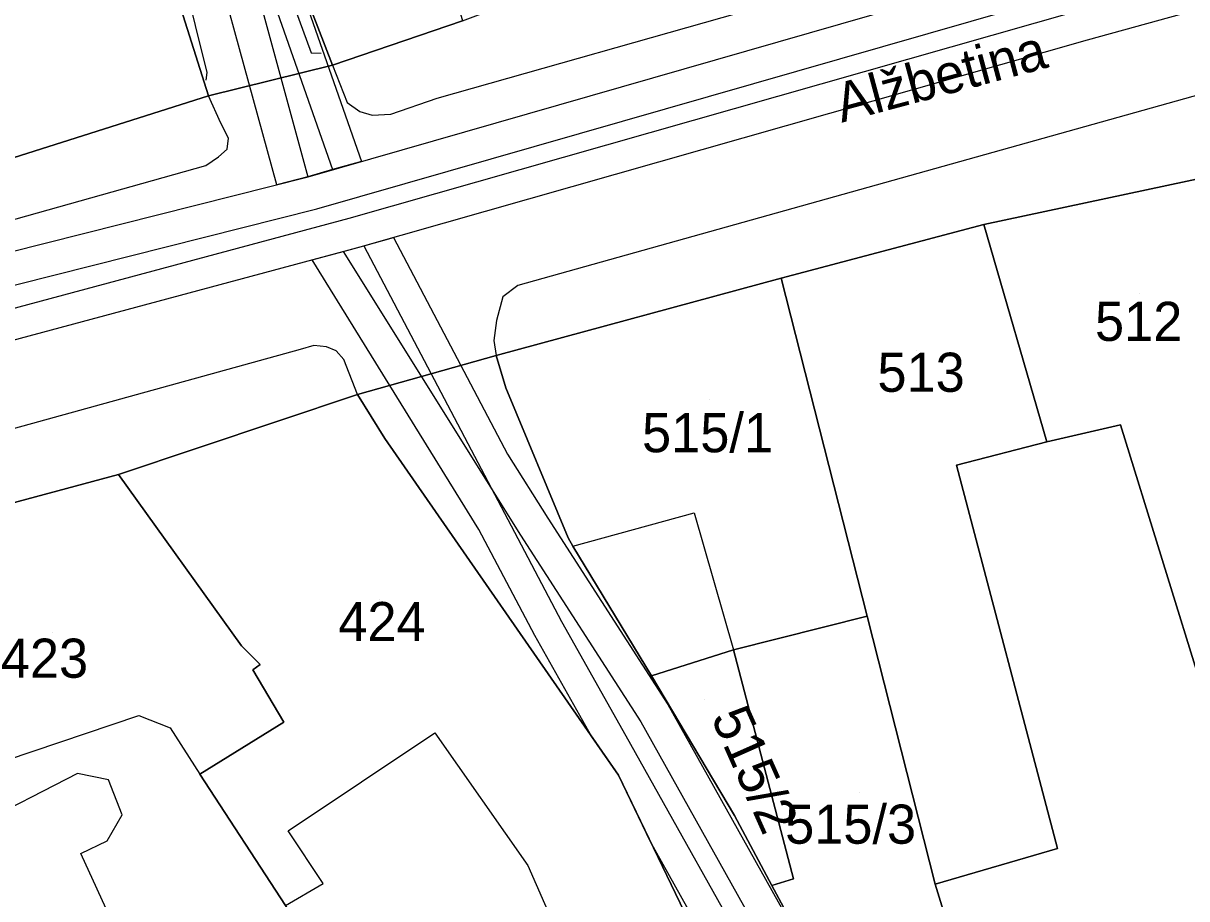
# Model space of a CAD drawing. Extents: x -263423 to -261326, y -1240067 to -1237864.
# Drawn here: x -263093.1 to -263033.7, y -1239708 to -1239663.3 of the extents above; entities that cross this region are included whole.
import ezdxf

# ---------------------------------------------------------------- set-up
doc = ezdxf.new("R2010")
doc.units = 0
for name, color, linetype in [('body_kn', 7, 'Continuous'), ('kladpar_druhypozemkov', 7, 'Continuous'), ('kladpar_hranice', 7, 'Continuous'), ('kladpar_parcelnecisla', 7, 'Continuous'), ('kladpar_plochy', 7, 'Continuous'), ('popisy', 7, 'Continuous'), ('tarchy_linie', 7, 'Continuous'), ('zappar_hrandruhpozemk', 7, 'Continuous')]:
    doc.layers.add(name, color=color, linetype=linetype)

msp = doc.modelspace()

# ---------------------------------------------------------------- linework, layer by layer
at = {"layer": 'body_kn'}
for p, q in [((-263038.78, -1239664.15), (-263038.78, -1239664.15)), ((-263078.42, -1239664.79), (-263078.42, -1239664.79)), ((-263077.91, -1239664.8), (-263077.91, -1239664.8)), ((-263077.34, -1239665.42), (-263077.34, -1239665.42)), ((-263077.34, -1239665.42), (-263077.34, -1239665.42)), ((-263083.76, -1239665.8), (-263083.76, -1239665.8)), ((-263083.8, -1239666.19), (-263083.8, -1239666.19)), ((-263083.66, -1239666.98), (-263083.66, -1239666.98)), ((-263071.98, -1239667.1), (-263071.98, -1239667.1)), ((-263076.58, -1239667.33), (-263076.58, -1239667.33)), ((-263075.94, -1239667.78), (-263075.94, -1239667.78)), ((-263083.03, -1239668.38), (-263083.03, -1239668.38)), ((-263075.3, -1239667.98), (-263075.3, -1239667.98)), ((-263074.35, -1239667.92), (-263074.35, -1239667.92)), ((-263082.65, -1239669.15), (-263082.65, -1239669.15)), ((-263083.16, -1239670.1), (-263083.16, -1239670.1)), ((-263082.71, -1239669.72), (-263082.71, -1239669.72)), ((-263083.8, -1239670.54), (-263083.8, -1239670.54)), ((-263077.34, -1239670.76), (-263077.34, -1239670.76)), ((-263075.85, -1239670.34), (-263075.85, -1239670.34)), ((-263078.59, -1239671.12), (-263078.59, -1239671.12)), ((-263078.58, -1239671.12), (-263078.58, -1239671.12)), ((-263080.18, -1239671.53), (-263080.18, -1239671.53)), ((-263078.14, -1239672.76), (-263078.14, -1239672.76)), ((-263076.48, -1239673.23), (-263076.48, -1239673.23)), ((-263044.06, -1239673.56), (-263044.06, -1239673.56)), ((-263044.06, -1239673.56), (-263044.06, -1239673.56)), ((-263074.22, -1239674.23), (-263074.22, -1239674.23)), ((-263074.22, -1239674.23), (-263074.22, -1239674.23)), ((-263076.78, -1239674.94), (-263076.78, -1239674.94)), ((-263076.78, -1239674.94), (-263076.78, -1239674.94)), ((-263076.06, -1239674.75), (-263076.06, -1239674.75)), ((-263075.73, -1239674.66), (-263075.73, -1239674.66)), ((-263075.73, -1239674.66), (-263075.73, -1239674.66)), ((-263078.38, -1239675.37), (-263078.38, -1239675.37)), ((-263067.87, -1239676.68), (-263067.87, -1239676.68)), ((-263054.41, -1239676.31), (-263054.41, -1239676.31)), ((-263054.41, -1239676.31), (-263054.41, -1239676.31)), ((-263068.64, -1239677.25), (-263068.64, -1239677.25)), ((-263068.96, -1239678.46), (-263068.96, -1239678.46)), ((-263078.28, -1239679.75), (-263078.28, -1239679.75)), ((-263069.09, -1239679.48), (-263069.09, -1239679.48)), ((-263078.99, -1239679.94), (-263078.99, -1239679.94)), ((-263077.64, -1239679.82), (-263077.64, -1239679.82)), ((-263077.14, -1239680.01), (-263077.14, -1239680.01)), ((-263068.97, -1239680.25), (-263068.97, -1239680.25)), ((-263076.75, -1239680.46), (-263076.75, -1239680.46)), ((-263068.47, -1239681.91), (-263068.47, -1239681.91)), ((-263076.06, -1239682.25), (-263076.06, -1239682.25)), ((-263076.06, -1239682.25), (-263076.06, -1239682.25)), ((-263037.08, -1239683.79), (-263037.08, -1239683.79)), ((-263074.66, -1239684.49), (-263074.66, -1239684.49)), ((-263040.85, -1239684.66), (-263040.85, -1239684.66)), ((-263068.39, -1239685.29), (-263068.39, -1239685.29)), ((-263045.45, -1239685.85), (-263045.45, -1239685.85)), ((-263088.26, -1239686.33), (-263088.26, -1239686.33)), ((-263088.26, -1239686.33), (-263088.26, -1239686.33)), ((-263066.33, -1239688.56), (-263066.33, -1239688.56)), ((-263058.85, -1239688.29), (-263058.85, -1239688.29)), ((-263069.85, -1239689.14), (-263069.85, -1239689.14)), ((-263067.73, -1239689.43), (-263067.73, -1239689.43)), ((-263065.3, -1239689.57), (-263065.3, -1239689.57)), ((-263065.05, -1239689.99), (-263065.05, -1239689.99)), ((-263065.05, -1239689.99), (-263065.05, -1239689.99)), ((-263065.63, -1239693.84), (-263065.63, -1239693.84)), ((-263050.02, -1239693.58), (-263050.02, -1239693.58)), ((-263067, -1239694.56), (-263067, -1239694.56)), ((-263081.98, -1239695.09), (-263081.98, -1239695.09)), ((-263056.85, -1239695.29), (-263056.85, -1239695.29)), ((-263056.85, -1239695.29), (-263056.85, -1239695.29)), ((-263081.41, -1239696.31), (-263081.41, -1239696.31)), ((-263081.02, -1239696.05), (-263081.02, -1239696.05)), ((-263061.03, -1239696.62), (-263061.03, -1239696.62)), ((-263061.03, -1239696.62), (-263061.03, -1239696.62)), ((-263060.2, -1239698.08), (-263060.2, -1239698.08)), ((-263087.22, -1239698.64), (-263087.22, -1239698.64)), ((-263085.63, -1239699.28), (-263085.63, -1239699.28)), ((-263079.82, -1239698.99), (-263079.82, -1239698.99)), ((-263061.59, -1239698.97), (-263061.59, -1239698.97)), ((-263072.11, -1239699.54), (-263072.11, -1239699.54)), ((-263064.09, -1239699.73), (-263064.09, -1239699.73)), ((-263062.34, -1239699.68), (-263062.34, -1239699.68)), ((-263090.36, -1239701.61), (-263090.36, -1239701.61)), ((-263084.11, -1239701.65), (-263084.11, -1239701.65)), ((-263062.73, -1239701.69), (-263062.73, -1239701.69)), ((-263088.77, -1239701.94), (-263088.77, -1239701.94)), ((-263088.07, -1239703.73), (-263088.07, -1239703.73)), ((-263056.8, -1239703.76), (-263056.8, -1239703.76)), ((-263079.59, -1239704.54), (-263079.59, -1239704.54)), ((-263088.84, -1239705.06), (-263088.84, -1239705.06)), ((-263061.08, -1239705.11), (-263061.08, -1239705.11)), ((-263090.19, -1239705.7), (-263090.19, -1239705.7)), ((-263040.29, -1239705.44), (-263040.29, -1239705.44)), ((-263040.29, -1239705.44), (-263040.29, -1239705.44)), ((-263067.35, -1239706.32), (-263067.35, -1239706.32)), ((-263053.79, -1239706.99), (-263053.79, -1239706.99)), ((-263077.81, -1239707.23), (-263077.81, -1239707.23)), ((-263054.89, -1239707.33), (-263054.89, -1239707.33)), ((-263046.55, -1239707.26), (-263046.55, -1239707.26))]:
    msp.add_line(p, q, dxfattribs=at)
at = {"layer": 'kladpar_druhypozemkov'}
for p, q in [((-263036.09, -1239677.08), (-263036.09, -1239677.08)), ((-263047.51, -1239680.02), (-263047.51, -1239680.02)), ((-263058.07, -1239682.49), (-263058.07, -1239682.49)), ((-263074.94, -1239692.7), (-263074.94, -1239692.7)), ((-263091.64, -1239694.43), (-263091.64, -1239694.43)), ((-263058.33, -1239697.85), (-263058.33, -1239697.85)), ((-263050.4, -1239702.57), (-263050.4, -1239702.57))]:
    msp.add_line(p, q, dxfattribs=at)
at = {"layer": 'kladpar_hranice'}
for points in [[(-263089.13, -1239646.3), (-263087.57, -1239654.65), (-263083.66, -1239666.98), (-263102.19, -1239672.87), (-263104.68, -1239658.71), (-263104.81, -1239658), (-263105.49, -1239653.48), (-263107, -1239647.48), (-263105.73, -1239647.36), (-263103.75, -1239647.24), (-263089.13, -1239646.3)], [(-263070.69, -1239663.16), (-263077.34, -1239665.42), (-263082.9, -1239650.98), (-263082.64, -1239650.86), (-263078.94, -1239649.73), (-263074.91, -1239648.54), (-263070.69, -1239663.16)], [(-263173.05, -1239691.46), (-263143.93, -1239683.63), (-263134.03, -1239681.02), (-263132.76, -1239680.64), (-263130.92, -1239680.26), (-263121.67, -1239678.18), (-263113.17, -1239675.87), (-263110.23, -1239675.06), (-263102.19, -1239672.87), (-263083.66, -1239666.98), (-263077.34, -1239665.42), (-263070.69, -1239663.16), (-263068.84, -1239662.46), (-263064.69, -1239661.08), (-263061.56, -1239660.4), (-263059.64, -1239659.9), (-263058.11, -1239659.46), (-263052.62, -1239657.71), (-263049.81, -1239656.96), (-263044.38, -1239655.39), (-263040.1, -1239654.14), (-263037.61, -1239653.45), (-263034.48, -1239652.64), (-263029.18, -1239651.14)], [(-263082.9, -1239650.98), (-263077.34, -1239665.42), (-263083.66, -1239666.98), (-263087.57, -1239654.65)], [(-263032.63, -1239671.13), (-263044.06, -1239673.56), (-263054.41, -1239676.31), (-263068.97, -1239680.25), (-263076.06, -1239682.25), (-263088.26, -1239686.33), (-263109.85, -1239692.14), (-263111.38, -1239692.39), (-263119.82, -1239694.51), (-263121.61, -1239695.01), (-263130.26, -1239696.9), (-263130.33, -1239696.59), (-263132.49, -1239697.1), (-263132.36, -1239697.54), (-263132.93, -1239697.67), (-263136.1, -1239698.43), (-263136.29, -1239698.5), (-263136.42, -1239698.18), (-263138.83, -1239698.75), (-263138.77, -1239699.07), (-263146.95, -1239701.04), (-263158.18, -1239703.72)], [(-263032.63, -1239671.13), (-263029.01, -1239691.42), (-263028.92, -1239700.15), (-263024.63, -1239712.22), (-263023.17, -1239716.24), (-263018.7, -1239730.16), (-263018.89, -1239730.86), (-263029.02, -1239727.36), (-263028.76, -1239726.41), (-263029.76, -1239720.92), (-263027.85, -1239720.48), (-263026.44, -1239718.2), (-263037.08, -1239683.79), (-263040.85, -1239684.66), (-263044.06, -1239673.56), (-263032.63, -1239671.13)], [(-263044.06, -1239673.56), (-263040.85, -1239684.66), (-263045.45, -1239685.85), (-263040.29, -1239705.44), (-263046.55, -1239707.26), (-263050.02, -1239693.58), (-263054.41, -1239676.31), (-263044.06, -1239673.56)], [(-263054.41, -1239676.31), (-263050.02, -1239693.58), (-263056.85, -1239695.29), (-263061.03, -1239696.62), (-263065.05, -1239689.99), (-263065.3, -1239689.57), (-263068.47, -1239681.91), (-263068.97, -1239680.25), (-263054.41, -1239676.31)], [(-263029.37, -1239734.56), (-263046.25, -1239727.85), (-263052.8, -1239721.7), (-263056.66, -1239714.28), (-263062.73, -1239701.69), (-263074.66, -1239684.49), (-263076.06, -1239682.25), (-263068.97, -1239680.25), (-263068.47, -1239681.91), (-263065.3, -1239689.57), (-263065.05, -1239689.99), (-263061.03, -1239696.62), (-263056.8, -1239703.76), (-263054.89, -1239707.33), (-263053.47, -1239709.96), (-263051.55, -1239713.54), (-263048.19, -1239718.6), (-263045.41, -1239721.07), (-263045.01, -1239721.42), (-263036.09, -1239724.78), (-263032.84, -1239725.88)], [(-263076.06, -1239682.25), (-263074.66, -1239684.49), (-263062.73, -1239701.69), (-263056.66, -1239714.28), (-263068.24, -1239723.85), (-263068.88, -1239724.42), (-263072.12, -1239720.58), (-263078.72, -1239710.03), (-263079.73, -1239708.36), (-263084.11, -1239701.65), (-263079.82, -1239698.99), (-263081.41, -1239696.31), (-263081.02, -1239696.05), (-263081.98, -1239695.09), (-263088.26, -1239686.33), (-263076.06, -1239682.25)], [(-263040.29, -1239705.44), (-263045.45, -1239685.85), (-263040.85, -1239684.66), (-263037.08, -1239683.79), (-263026.44, -1239718.2), (-263027.85, -1239720.48), (-263029.76, -1239720.92), (-263028.76, -1239726.41), (-263029.02, -1239727.36), (-263032.84, -1239725.88), (-263036.09, -1239724.78), (-263045.01, -1239721.42), (-263042.33, -1239720.98), (-263046.55, -1239707.26), (-263040.29, -1239705.44)], [(-263088.26, -1239686.33), (-263081.98, -1239695.09), (-263081.02, -1239696.05), (-263081.41, -1239696.31), (-263079.82, -1239698.99), (-263084.11, -1239701.65), (-263079.73, -1239708.36), (-263078.72, -1239710.03), (-263079.17, -1239710.28), (-263086.39, -1239713.94), (-263088.82, -1239715.07), (-263090.93, -1239715.95), (-263096.62, -1239719.81), (-263109.85, -1239692.14), (-263088.26, -1239686.33)], [(-263056.85, -1239695.29), (-263050.02, -1239693.58), (-263046.55, -1239707.26), (-263042.33, -1239720.98), (-263045.01, -1239721.42), (-263045.41, -1239721.07), (-263048.19, -1239718.6), (-263051.55, -1239713.54), (-263053.47, -1239709.96), (-263054.89, -1239707.33), (-263053.79, -1239706.99), (-263056.85, -1239695.29)], [(-263061.03, -1239696.62), (-263056.85, -1239695.29), (-263053.79, -1239706.99), (-263054.89, -1239707.33), (-263056.8, -1239703.76), (-263061.03, -1239696.62)]]:
    msp.add_lwpolyline(points, dxfattribs=at)
at = {"layer": 'kladpar_plochy'}
for points in [[(-263089.13, -1239646.3), (-263087.57, -1239654.65), (-263083.66, -1239666.98), (-263102.19, -1239672.87), (-263104.68, -1239658.71), (-263104.81, -1239658), (-263105.49, -1239653.48), (-263107, -1239647.48), (-263105.73, -1239647.36), (-263103.75, -1239647.24)], [(-263070.69, -1239663.16), (-263077.34, -1239665.42), (-263082.9, -1239650.98), (-263082.64, -1239650.86), (-263078.94, -1239649.73), (-263074.91, -1239648.54)], [(-263032.63, -1239671.13), (-263029.01, -1239691.42), (-263028.92, -1239700.15), (-263024.63, -1239712.22), (-263023.17, -1239716.24), (-263018.7, -1239730.16), (-263018.89, -1239730.86), (-263029.02, -1239727.36), (-263028.76, -1239726.41), (-263029.76, -1239720.92), (-263027.85, -1239720.48), (-263026.44, -1239718.2), (-263037.08, -1239683.79), (-263040.85, -1239684.66), (-263044.06, -1239673.56)], [(-263044.06, -1239673.56), (-263040.85, -1239684.66), (-263045.45, -1239685.85), (-263040.29, -1239705.44), (-263046.55, -1239707.26), (-263050.02, -1239693.58), (-263054.41, -1239676.31)], [(-263054.41, -1239676.31), (-263050.02, -1239693.58), (-263056.85, -1239695.29), (-263061.03, -1239696.62), (-263065.05, -1239689.99), (-263065.3, -1239689.57), (-263068.47, -1239681.91), (-263068.97, -1239680.25)], [(-263076.06, -1239682.25), (-263074.66, -1239684.49), (-263062.73, -1239701.69), (-263056.66, -1239714.28), (-263068.24, -1239723.85), (-263068.88, -1239724.42), (-263072.12, -1239720.58), (-263078.72, -1239710.03), (-263079.73, -1239708.36), (-263084.11, -1239701.65), (-263079.82, -1239698.99), (-263081.41, -1239696.31), (-263081.02, -1239696.05), (-263081.98, -1239695.09), (-263088.26, -1239686.33)], [(-263040.29, -1239705.44), (-263045.45, -1239685.85), (-263040.85, -1239684.66), (-263037.08, -1239683.79), (-263026.44, -1239718.2), (-263027.85, -1239720.48), (-263029.76, -1239720.92), (-263028.76, -1239726.41), (-263029.02, -1239727.36), (-263032.84, -1239725.88), (-263036.09, -1239724.78), (-263045.01, -1239721.42), (-263042.33, -1239720.98), (-263046.55, -1239707.26)], [(-263088.26, -1239686.33), (-263081.98, -1239695.09), (-263081.02, -1239696.05), (-263081.41, -1239696.31), (-263079.82, -1239698.99), (-263084.11, -1239701.65), (-263079.73, -1239708.36), (-263078.72, -1239710.03), (-263079.17, -1239710.28), (-263086.39, -1239713.94), (-263088.82, -1239715.07), (-263090.93, -1239715.95), (-263096.62, -1239719.81), (-263109.85, -1239692.14)], [(-263056.85, -1239695.29), (-263050.02, -1239693.58), (-263046.55, -1239707.26), (-263042.33, -1239720.98), (-263045.01, -1239721.42), (-263045.41, -1239721.07), (-263048.19, -1239718.6), (-263051.55, -1239713.54), (-263053.47, -1239709.96), (-263054.89, -1239707.33), (-263053.79, -1239706.99)], [(-263061.03, -1239696.62), (-263056.85, -1239695.29), (-263053.79, -1239706.99), (-263054.89, -1239707.33), (-263056.8, -1239703.76)]]:
    msp.add_lwpolyline(points, close=True, dxfattribs=at)
for points in [[(-263173.05, -1239691.46), (-263143.93, -1239683.63), (-263134.03, -1239681.02), (-263132.76, -1239680.64), (-263130.92, -1239680.26), (-263121.67, -1239678.18), (-263113.17, -1239675.87), (-263110.23, -1239675.06), (-263102.19, -1239672.87), (-263083.66, -1239666.98), (-263077.34, -1239665.42), (-263070.69, -1239663.16), (-263068.84, -1239662.46), (-263064.69, -1239661.08), (-263061.56, -1239660.4), (-263059.64, -1239659.9), (-263058.11, -1239659.46), (-263052.62, -1239657.71), (-263049.81, -1239656.96), (-263044.38, -1239655.39), (-263040.1, -1239654.14), (-263037.61, -1239653.45), (-263034.48, -1239652.64), (-263029.18, -1239651.14)], [(-263082.9, -1239650.98), (-263077.34, -1239665.42), (-263083.66, -1239666.98), (-263087.57, -1239654.65)], [(-263032.63, -1239671.13), (-263044.06, -1239673.56), (-263054.41, -1239676.31), (-263068.97, -1239680.25), (-263076.06, -1239682.25), (-263088.26, -1239686.33), (-263109.85, -1239692.14), (-263111.38, -1239692.39), (-263119.82, -1239694.51), (-263121.61, -1239695.01), (-263130.26, -1239696.9), (-263130.33, -1239696.59), (-263132.49, -1239697.1), (-263132.36, -1239697.54), (-263132.93, -1239697.67), (-263136.1, -1239698.43), (-263136.29, -1239698.5), (-263136.42, -1239698.18), (-263138.83, -1239698.75), (-263138.77, -1239699.07), (-263146.95, -1239701.04), (-263158.18, -1239703.72)], [(-263029.37, -1239734.56), (-263046.25, -1239727.85), (-263052.8, -1239721.7), (-263056.66, -1239714.28), (-263062.73, -1239701.69), (-263074.66, -1239684.49), (-263076.06, -1239682.25), (-263068.97, -1239680.25), (-263068.47, -1239681.91), (-263065.3, -1239689.57), (-263065.05, -1239689.99), (-263061.03, -1239696.62), (-263056.8, -1239703.76), (-263054.89, -1239707.33), (-263053.47, -1239709.96), (-263051.55, -1239713.54), (-263048.19, -1239718.6), (-263045.41, -1239721.07), (-263045.01, -1239721.42), (-263036.09, -1239724.78), (-263032.84, -1239725.88)]]:
    msp.add_lwpolyline(points, dxfattribs=at)
at = {"layer": 'tarchy_linie'}
for points in [[(-263090.53, -1239561.28), (-263090.87, -1239568.64), (-263092.33, -1239569.96), (-263091.83, -1239582.66), (-263092.15, -1239592.45), (-263091.08, -1239610.48), (-263090.31, -1239618.39), (-263089.47, -1239627.24), (-263088.6, -1239634.2), (-263087.59, -1239641.45), (-263084.65, -1239649.87), (-263077.34, -1239670.76)], [(-263092.85, -1239561.66), (-263092.5, -1239567.49), (-263091.91, -1239599.94), (-263087.68, -1239638.49), (-263083.16, -1239654.37), (-263078.59, -1239671.12)], [(-263179.85, -1239698.42), (-263173.88, -1239697.59), (-263170.87, -1239699.01), (-263120.93, -1239685.18), (-263076.48, -1239673.23), (-263039.2, -1239662.63), (-262985.5, -1239647.83), (-262924.66, -1239632.02), (-262915.43, -1239631.16), (-262840.91, -1239608.6), (-262834.87, -1239603.16), (-262831.96, -1239601.93), (-262815.48, -1239596.45)], [(-263185.2, -1239701.74), (-263151.5, -1239692.2), (-263118.32, -1239682.9), (-263078.14, -1239672.76), (-263026.9, -1239658.04), (-262972.11, -1239643.08), (-262917.68, -1239628.4), (-262867.28, -1239613.64), (-262817.29, -1239598.81)], [(-263090.26, -1239632.1), (-263089.28, -1239639), (-263088.37, -1239645.45), (-263087.12, -1239652.38), (-263085.93, -1239657.06), (-263085.54, -1239658.58), (-263083.76, -1239665.8), (-263083.8, -1239666.19)], [(-262985.09, -1239649.35), (-263038.78, -1239664.15), (-263076.06, -1239674.75), (-263117.13, -1239685.79), (-263120.29, -1239686.64), (-263120.52, -1239686.7), (-263121.79, -1239687.05), (-263170.45, -1239700.53), (-263171.54, -1239700.43), (-263172.59, -1239699.94), (-263184.74, -1239703.38), (-263185.2, -1239701.74), (-263185.66, -1239700.1)], [(-263079.87, -1239658.84), (-263075.85, -1239670.34), (-263077.34, -1239670.76), (-263078.59, -1239671.12), (-263080.18, -1239671.53), (-263084.75, -1239654.82)], [(-263185.66, -1239700.1), (-263179.84, -1239698.46), (-263179.85, -1239698.42), (-263180.07, -1239696.86), (-263174.1, -1239696.03), (-263173.21, -1239696.17), (-263172.66, -1239696.42), (-263151.96, -1239690.56), (-263118.76, -1239681.26), (-263078.58, -1239671.12), (-263027.36, -1239656.4)], [(-263085.54, -1239658.58), (-263081.3, -1239656.93), (-263078.42, -1239664.79), (-263077.91, -1239664.8)], [(-263029.37, -1239734.56), (-263042.62, -1239729.29), (-263047.72, -1239726.47), (-263051.32, -1239723.09), (-263056.4, -1239713.49), (-263061.08, -1239705.11), (-263062.73, -1239701.69), (-263064.09, -1239699.73), (-263067, -1239694.56), (-263069.85, -1239689.14), (-263078.38, -1239675.37), (-263076.78, -1239674.94), (-263075.73, -1239674.66), (-263074.22, -1239674.23)], [(-263074.22, -1239674.23), (-263068.39, -1239685.29), (-263066.33, -1239688.56), (-263060.2, -1239698.08), (-263046.83, -1239721.99), (-262992.42, -1239741.82)], [(-263076.78, -1239674.94), (-263067.73, -1239689.43), (-263061.59, -1239698.97), (-263048.27, -1239722.8), (-262993, -1239743.37), (-262958.92, -1239752.71), (-262923.54, -1239762), (-262867.86, -1239773.48), (-262824.56, -1239787.75), (-262785.95, -1239791.48), (-262742.38, -1239779.12)], [(-263075.73, -1239674.66), (-263065.63, -1239693.84), (-263062.34, -1239699.68), (-263055.05, -1239712.73), (-263048.91, -1239724.32), (-263038.17, -1239729.99), (-263026.79, -1239734.46)]]:
    msp.add_lwpolyline(points, dxfattribs=at)
at = {"layer": 'zappar_hrandruhpozemk'}
for p, q in [((-263078.99, -1239679.94), (-263110.35, -1239688.63)), ((-263065.05, -1239689.99), (-263058.85, -1239688.29)), ((-263058.85, -1239688.29), (-263056.85, -1239695.29)), ((-263079.59, -1239704.54), (-263072.11, -1239699.54)), ((-263086.39, -1239713.94), (-263090.19, -1239705.7))]:
    msp.add_line(p, q, dxfattribs=at)
for points in [[(-263077.34, -1239665.42), (-263076.58, -1239667.33), (-263075.94, -1239667.78), (-263075.3, -1239667.98), (-263074.35, -1239667.92), (-263071.98, -1239667.1), (-263055.63, -1239662.47), (-263017.64, -1239651.71)], [(-263032.11, -1239666.67), (-263067.87, -1239676.68), (-263068.64, -1239677.25), (-263068.96, -1239678.46), (-263069.09, -1239679.48), (-263068.97, -1239680.25)], [(-263099.39, -1239674.92), (-263083.8, -1239670.54), (-263083.16, -1239670.1), (-263082.71, -1239669.72), (-263082.65, -1239669.15), (-263083.03, -1239668.38), (-263083.66, -1239666.98)], [(-263076.06, -1239682.25), (-263076.75, -1239680.46), (-263077.14, -1239680.01), (-263077.64, -1239679.82), (-263078.28, -1239679.75), (-263078.99, -1239679.94)], [(-263090.19, -1239705.7), (-263088.84, -1239705.06), (-263088.07, -1239703.73), (-263088.77, -1239701.94), (-263090.36, -1239701.61), (-263095.67, -1239704.33), (-263096.68, -1239701.84), (-263087.22, -1239698.64), (-263085.63, -1239699.28), (-263084.11, -1239701.65)], [(-263072.11, -1239699.54), (-263067.35, -1239706.32), (-263064.06, -1239713.8), (-263072.12, -1239720.58)], [(-263079.73, -1239708.36), (-263077.81, -1239707.23), (-263079.59, -1239704.54)]]:
    msp.add_lwpolyline(points, dxfattribs=at)

# ---------------------------------------------------------------- texts
at = {"layer": 'kladpar_parcelnecisla'}
for s, p in [('512', (-263038.381, -1239679.51)), ('513', (-263049.497, -1239682.11)), ('515/1', (-263061.52, -1239685.2)), ('424', (-263077.036, -1239694.85)), ('423', (-263094.278, -1239696.72)), ('515/3', (-263054.212, -1239705.2))]:
    msp.add_text(s, height=2, dxfattribs=at).set_placement(p)
msp.add_text('515/2', height=2, rotation=294, dxfattribs=at).set_placement((-263058.02, -1239698.741))
at = {"layer": 'popisy'}
msp.add_text('Alžbetina', height=2, rotation=15, dxfattribs=at).set_placement((-263051.324, -1239668.365))

doc.saveas('drawing.dxf')
